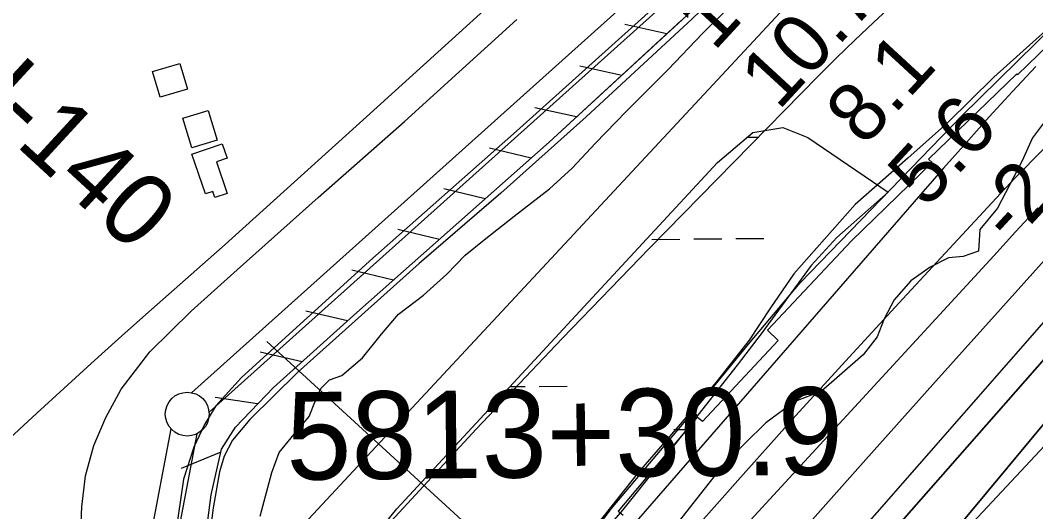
# Model space of a CAD drawing. Extents: x 3598634 to 3636690, y 517270 to 542944.
# Drawn here: x 3606399 to 3607559, y 531870 to 532431 of the extents above; entities that cross this region are included whole.
import ezdxf

# ---------------------------------------------------------------- set-up
doc = ezdxf.new("R2010")
doc.units = 0
for name, color, linetype in [('V-BLDG-OTLN', 7, 'Continuous'), ('V-FLOD-BASE', 7, 'Continuous'), ('V-LEVE-TOET', 7, 'Continuous'), ('V-RIVR-EDGE', 7, 'Continuous'), ('V-RIVR-RANG', 7, 'Continuous'), ('V-RIVR-RANG-IDEN', 7, 'Continuous'), ('V-ROAD-CNTR', 7, 'Continuous'), ('V-RRAP-FSHR', 7, 'Continuous'), ('V-RRAP-RVMT', 7, 'Continuous'), ('V-SITE-VEGE', 7, 'Continuous'), ('V-SURV-IDEN', 7, 'Continuous'), ('V-SURV-LINE', 7, 'Continuous'), ('V-TOPO-DPTH', 7, 'Continuous'), ('V-TOPO-MINR', 7, 'Continuous'), ('V-TOPO-WATR', 7, 'Continuous'), ('V-WETL-SWMP', 7, 'Continuous')]:
    doc.layers.add(name, color=color, linetype=linetype)

msp = doc.modelspace()

# ---------------------------------------------------------------- linework, layer by layer
at = {"layer": 'V-BLDG-OTLN'}
for points in [[(3606558.9, 532342.9), (3606550.2, 532372.2), (3606581.3, 532381.5), (3606590.1, 532352.2)], [(3606614, 532327.8), (3606624.1, 532293.7), (3606595, 532285), (3606584.9, 532319.1)], [(3606623.4, 532269.2), (3606635.5, 532233.1), (3606621.5, 532228.3), (3606619.1, 532235.3), (3606610.6, 532232.5), (3606595.3, 532277.8), (3606630, 532289.5), (3606635.4, 532273.2)]]:
    msp.add_lwpolyline(points, close=True, dxfattribs=at)
at = {"layer": 'V-FLOD-BASE'}
msp.add_lwpolyline([(3607131.3, 532452.3), (3606965.8, 532304), (3606801.7, 532159.1), (3606651.9, 532023), (3606622.6, 531990.5), (3606609.6, 531969.5), (3606597.3, 531943.7), (3606585.6, 531907.1), (3606579.4, 531865), (3606569.7, 531795.7), (3606561.5, 531769.2), (3606546.5, 531738.7), (3606517.8, 531695.3), (3606461.2, 531631), (3606393.8, 531563.9)], dxfattribs=at)
at = {"layer": 'V-LEVE-TOET'}
for points in [[(3607580.8, 532806.7), (3607479.3, 532720), (3607360.9, 532617.8), (3607272.3, 532533.8), (3607166.7, 532432.2), (3607045.5, 532320.5), (3606948.1, 532233.2), (3606854.9, 532153.3), (3606715.9, 532028.7), (3606661.5, 531975.2), (3606641.7, 531951.5), (3606632.1, 531933.2), (3606626.6, 531915.5), (3606619.7, 531874.1)], [(3606347.9, 531665.3), (3606407.9, 531731.6), (3606434.4, 531762.1), (3606446, 531777), (3606457.7, 531803.5), (3606463.8, 531824.5), (3606468.6, 531848.3), (3606469.4, 531875.5), (3606473.6, 531910.8), (3606483.2, 531945.4), (3606496.9, 531977.3), (3606514.6, 532009.8), (3606547.3, 532052.5), (3606594.3, 532098.6), (3606646.8, 532146), (3606739.4, 532228.6), (3606838.1, 532315.2), (3606966.2, 532431.7)], [(3606619.7, 531874.1), (3606606.5, 531772.9), (3606598.3, 531747.8), (3606579.2, 531711.9), (3606555.3, 531673.9), (3606532.1, 531646.1), (3606494.7, 531605.5), (3606428.6, 531534.3), (3606332.5, 531435.4), (3606250.1, 531349.4), (3606213.3, 531314.2), (3606139.1, 531242.4), (3606000.1, 531109.7), (3605968.1, 531071.7), (3605947.6, 531042.6), (3605936, 531022.9), (3605928.5, 531002.6), (3605923.7, 530974), (3605909.9, 530921.8), (3605898.3, 530885.8), (3605874.4, 530845.1), (3605845.1, 530801.7), (3605764.7, 530709.6)]]:
    msp.add_lwpolyline(points, dxfattribs=at)
at = {"layer": 'V-RIVR-EDGE'}
msp.add_lwpolyline([(3607568.7, 532314.8), (3607555.2, 532296.4), (3607542.9, 532269.5), (3607515.2, 532216.3), (3607494.9, 532191.8), (3607493.6, 532167.3), (3607475.8, 532161.2), (3607459.3, 532159.4), (3607438.4, 532149.1), (3607416.3, 532133.2), (3607397.3, 532111.8), (3607385.6, 532089.8), (3607377.6, 532069.6), (3607361.6, 532048.8), (3607313.7, 532007.2), (3607283.6, 531995.7), (3607250.5, 531971.2), (3607202.6, 531924.2), (3607175.5, 531889.9), (3607152.2, 531860)], dxfattribs=at)
at = {"layer": 'V-RIVR-RANG'}
msp.add_line((3606681, 532064.1), (3607374.3, 531429.2), dxfattribs=at)
at = {"layer": 'V-ROAD-CNTR'}
msp.add_lwpolyline([(3606387.4, 531953.7), (3606418.2, 531982.2), (3606449.1, 532010.6), (3606480.2, 532038.9), (3606511.3, 532067), (3606542.6, 532095), (3606633.2, 532174.9), (3606794.6, 532320.4), (3606941, 532453.2)], dxfattribs=at)
at = {"layer": 'V-RRAP-FSHR'}
for p, q in [((3607137.5, 532415.2), (3607089.8, 532425.7)), ((3607086.1, 532367.8), (3607038.4, 532378.3)), ((3607034.6, 532320.4), (3606986.9, 532330.8)), ((3606982.7, 532273.4), (3606935.2, 532284.8)), ((3606930.3, 532227), (3606882.8, 532238.4)), ((3606877.9, 532180.6), (3606830.4, 532192)), ((3606825.4, 532134.2), (3606777.9, 532145.6)), ((3606773.1, 532087.8), (3606725.5, 532098.8)), ((3606721, 532041), (3606673.4, 532052)), ((3606670.3, 531992.8), (3606622, 532000.3)), ((3606628.2, 531937.8), (3606582.9, 531919.3))]:
    msp.add_line(p, q, dxfattribs=at)
for points in [[(3605820.9, 530227.4), (3606036.1, 530488.4), (3606189.3, 530713.3), (3606419.6, 531040.7), (3606531.1, 531185.8), (3606653.3, 531360.7), (3606830.6, 531572), (3606913.7, 531664.9), (3606995.7, 531768), (3607074.2, 531873.3), (3607165.6, 531981.6), (3607231, 532060.9), (3607289.9, 532131), (3607473.9, 532321.1), (3607836.1, 532677), (3607900.4, 532747.2), (3608145, 532976.3), (3608226.2, 533101.7), (3608431.6, 533291.6), (3608655.7, 533489.7), (3608731.3, 533575.9), (3608845.3, 533667.2), (3608960.4, 533749.3)], [(3604875.1, 529685.7), (3605090, 529929.6), (3605236.8, 530108), (3605464.9, 530364.9), (3605751.9, 530707.6), (3605853.7, 530832.3), (3605888.7, 530881.3), (3605915.9, 530970.2), (3605940.9, 531032.9), (3605978.4, 531089.9), (3606027.7, 531141.9), (3606259.9, 531369.8), (3606464.4, 531577.9), (3606550.8, 531679.8), (3606587.9, 531739.7), (3606600.6, 531772.1), (3606609.7, 531830.4), (3606617.1, 531889.3), (3606629, 531941.4), (3606644.9, 531966.5), (3606688.5, 532011.7), (3606783.7, 532097.3), (3607003.1, 532291.4), (3607274.6, 532541.5)], [(3606562, 531697.8), (3606587.9, 531739.7), (3606600.6, 531772.1), (3606609.7, 531830.4), (3606617.1, 531889.3), (3606629, 531941.4), (3606644.9, 531966.5), (3606688.5, 532011.7), (3606783.7, 532097.3), (3607003.1, 532291.4), (3607153.9, 532430.3)]]:
    msp.add_lwpolyline(points, dxfattribs=at)
at = {"layer": 'V-RRAP-RVMT'}
for p, q in [((3607721.9, 532546.8), (3607538.2, 532368.5)), ((3607537.1, 532369.4), (3607436.5, 532272.2)), ((3607538.2, 532368.5), (3607537.1, 532369.4)), ((3607440.5, 532268.2), (3607348.3, 532179.1)), ((3607436.5, 532272.2), (3607440.5, 532268.2)), ((3607348.3, 532179.1), (3607252.7, 532077)), ((3607252.7, 532077), (3607264.7, 532065.4)), ((3607264.7, 532065.4), (3607178.3, 531972.8)), ((3607172.2, 531977.8), (3607082.1, 531870.6)), ((3607178.3, 531972.8), (3607172.2, 531977.8)), ((3607487.4, 531858), (3607568.7, 531945)), ((3607082.1, 531870.6), (3607087.7, 531865.8))]:
    msp.add_line(p, q, dxfattribs=at)
at = {"layer": 'V-SITE-VEGE'}
for p, q in [((3607178.3, 532415.4), (3607209, 532446)), ((3607606, 532451.1), (3607511.1, 532365.7)), ((3607139.2, 532374.4), (3607178.3, 532415.4)), ((3607091, 532326.5), (3607139.2, 532374.4)), ((3607511.1, 532365.7), (3607458, 532313.6)), ((3607056.1, 532290.4), (3607091, 532326.5)), ((3607458, 532313.6), (3607412.6, 532273.4)), ((3607029.5, 532261.9), (3607056.1, 532290.4)), ((3607412.6, 532273.4), (3607352.6, 532220.6)), ((3607003.7, 532238.3), (3607029.5, 532261.9)), ((3606963.2, 532207.1), (3607003.7, 532238.3)), ((3607352.6, 532220.6), (3607282.7, 532141.4)), ((3606929, 532180), (3606963.2, 532207.1)), ((3606907.4, 532162.7), (3606929, 532180)), ((3606886.4, 532141.1), (3606907.4, 532162.7)), ((3606859.9, 532116.8), (3606886.4, 532141.1)), ((3607282.7, 532141.4), (3607256.1, 532102.5)), ((3606831.3, 532095.3), (3606859.9, 532116.8)), ((3606811.7, 532072.4), (3606831.3, 532095.3)), ((3607256.1, 532102.5), (3607231.6, 532065.6)), ((3606790, 532045.3), (3606811.7, 532072.4)), ((3607231.6, 532065.6), (3607193.9, 532017.7)), ((3606766.3, 532025.2), (3606790, 532045.3)), ((3606752.3, 532020.3), (3606766.3, 532025.2)), ((3606742.6, 532010.6), (3606752.3, 532020.3)), ((3607193.9, 532017.7), (3607150.6, 531967)), ((3606736.3, 531996.7), (3606742.6, 532010.6)), ((3606729.2, 531978.6), (3606736.3, 531996.7)), ((3606715.3, 531962.6), (3606729.2, 531978.6)), ((3607150.6, 531967), (3607105.1, 531914.9)), ((3606695, 531937.6), (3606715.3, 531962.6)), ((3606686.6, 531914.7), (3606695, 531937.6)), ((3606673.2, 531864.6), (3606686.6, 531914.7)), ((3607105.1, 531914.9), (3607044.3, 531838.4))]:
    msp.add_line(p, q, dxfattribs=at)
at = {"layer": 'V-SURV-LINE'}
for points in [[(3606594.7, 532005.7), (3607952.8, 533222.8)], [(3607972.9, 533200.5), (3606614.8, 531983.4)], [(3606541.2, 531804.1), (3606571.4, 531964.4)], [(3606600.9, 531958.8), (3606570.6, 531798.5)]]:
    msp.add_lwpolyline(points, dxfattribs=at)
msp.add_circle((3606589.9, 531981.2), 25, dxfattribs=at)
at = {"layer": 'V-TOPO-DPTH'}
for points in [[(3607983.4, 532707.3), (3607541.5, 532257), (3607535.7, 532251.1), (3607529.9, 532245.1), (3607524.2, 532239.1), (3607518.5, 532233), (3607407, 532112.8), (3607345.8, 532046.4), (3607285, 531979.6), (3607224.8, 531912.4), (3607164.8, 531844.8), (3606773.7, 531400.4), (3606760.3, 531385), (3606747.1, 531369.4), (3606734.1, 531353.7), (3606064.8, 530299.3)], [(3606064.8, 530299.3), (3606734.1, 531353.7), (3606747.1, 531369.4), (3606760.3, 531385), (3606773.7, 531400.4), (3607164.8, 531844.8), (3607224.8, 531912.4), (3607285, 531979.6), (3607345.8, 532046.4), (3607407, 532112.8), (3607518.5, 532233), (3607524.2, 532239.1), (3607529.9, 532245.1), (3607535.7, 532251.1), (3607541.5, 532257), (3607983.4, 532707.3)], [(3607395, 532447.9), (3607373.4, 532428.1), (3607352.1, 532408), (3607331.1, 532387.5), (3607310.4, 532366.8), (3607117.7, 532170.5), (3607018.2, 532067.7), (3606919.8, 531964), (3606822.7, 531858.9), (3606726.7, 531752.9), (3606543.7, 531548.1), (3606539.9, 531543.8), (3606536.2, 531539.5), (3606532.5, 531535.2), (3606528.8, 531530.8), (3606474, 531465.6), (3606443.1, 531428.5), (3606412.5, 531391.1), (3606382.4, 531353.3), (3606352.5, 531315.4), (3605991.8, 530851.1), (3605962, 530812.4)], [(3607575.6, 532164.4), (3607441.4, 532015.1), (3607364.9, 531929.5), (3607288.8, 531843.7), (3607213.3, 531757.4), (3607138.1, 531670.7), (3606851.2, 531338.4), (3606838, 531322.6), (3606825.1, 531306.5), (3606812.7, 531290.1), (3606800.6, 531273.4), (3606710.9, 531145), (3606687.7, 531111.2), (3606665, 531077.1), (3606642.9, 531042.5), (3606621.2, 531007.7), (3606599.5, 530972.8), (3606577.5, 530938.2), (3606555, 530903.9), (3606532.1, 530869.9), (3606459.8, 530764.4)], [(3606459.8, 530764.4), (3606532.1, 530869.9), (3606555, 530903.9), (3606577.5, 530938.2), (3606599.5, 530972.8), (3606621.2, 531007.7), (3606642.9, 531042.5), (3606665, 531077.1), (3606687.7, 531111.2), (3606710.9, 531145), (3606800.6, 531273.4), (3606812.7, 531290.1), (3606825.1, 531306.5), (3606838, 531322.6), (3606851.2, 531338.4), (3607138.1, 531670.7), (3607213.3, 531757.4), (3607288.8, 531843.7), (3607364.9, 531929.5), (3607441.4, 532015.1), (3607575.6, 532164.4)], [(3606570.4, 530814.7), (3606635, 530902), (3606699.7, 530989.3), (3606764.3, 531076.6), (3606862.8, 531209.4), (3606878.4, 531230.2), (3606894.2, 531250.8), (3606910.2, 531271.2), (3606926.4, 531291.5), (3607025.4, 531413.8), (3607091.8, 531494.7), (3607158.8, 531575.1), (3607226.8, 531654.6), (3607295.4, 531733.7), (3607612.9, 532094.7)], [(3607612.9, 532094.7), (3607295.4, 531733.7), (3607226.8, 531654.6), (3607158.8, 531575.1), (3607091.8, 531494.7), (3607025.4, 531413.8), (3606926.4, 531291.5), (3606910.2, 531271.2), (3606894.2, 531250.8), (3606878.4, 531230.2), (3606862.8, 531209.4), (3606764.3, 531076.6), (3606699.7, 530989.3), (3606635, 530902), (3606570.4, 530814.7)], [(3606603.6, 530726), (3606689.7, 530846.3), (3606775.3, 530967), (3606917.5, 531169), (3606931.6, 531188.8), (3606945.8, 531208.6), (3606960.2, 531228.3), (3606974.8, 531247.9), (3606989.5, 531267.3), (3607004.4, 531286.6), (3607019.5, 531305.7), (3607034.8, 531324.7), (3607113.6, 531421.1), (3607168.4, 531488.1), (3607223.5, 531555.1), (3607278.6, 531621.8), (3607333.9, 531688.5), (3607575.6, 531979.3)], [(3607575.6, 531979.3), (3607333.9, 531688.5), (3607278.6, 531621.8), (3607223.5, 531555.1), (3607168.4, 531488.1), (3607113.6, 531421.1), (3607034.8, 531324.7), (3607019.5, 531305.7), (3607004.4, 531286.6), (3606989.5, 531267.3), (3606974.8, 531247.9), (3606960.2, 531228.3), (3606945.8, 531208.6), (3606931.6, 531188.8), (3606917.5, 531169), (3606775.3, 530967), (3606689.7, 530846.3), (3606603.6, 530726)]]:
    msp.add_lwpolyline(points, dxfattribs=at)
at = {"layer": 'V-TOPO-MINR'}
for points in [[(3607781.2, 532936.8), (3607320.2, 532493.6), (3607305.4, 532479), (3607290.7, 532464.3), (3607276.2, 532449.4), (3607261.9, 532434.3), (3606702.8, 531834.1), (3606665.1, 531793.2), (3606627.6, 531751.9), (3606590.6, 531710.2), (3606554, 531668.3), (3606534.8, 531646.1), (3606508, 531615), (3606481.3, 531583.8), (3606454.7, 531552.5), (3606428.2, 531521.1), (3605876.9, 530865)], [(3607395, 532447.9), (3607373.4, 532428.1), (3607352.1, 532408), (3607331.1, 532387.5), (3607310.4, 532366.8), (3607117.7, 532170.5), (3607018.2, 532067.7), (3606919.8, 531964), (3606822.7, 531858.9), (3606726.7, 531752.9), (3606543.7, 531548.1), (3606539.9, 531543.8), (3606536.2, 531539.5), (3606532.5, 531535.2), (3606528.8, 531530.8), (3606474, 531465.6), (3606443.1, 531428.5), (3606412.5, 531391.1), (3606382.4, 531353.3), (3606352.5, 531315.4), (3605991.8, 530851.1), (3605962, 530812.4)], [(3607558.8, 532378.1), (3607532.2, 532349.4), (3607505.8, 532320.3), (3607479.6, 532291.2), (3607453.6, 532261.9), (3607427.8, 532232.4), (3606790.6, 531500), (3606776.6, 531483.7), (3606762.7, 531467.3), (3606748.9, 531450.8), (3606735.2, 531434.2), (3606721.7, 531417.5), (3606708.3, 531400.7), (3606695, 531383.8), (3606681.9, 531366.8), (3606306.8, 530876.9), (3606243.5, 530794)], [(3607561.2, 532216.5), (3607535.9, 532189.2), (3607510.8, 532161.9), (3607206.4, 531831.2), (3607133.3, 531751.5), (3607060.3, 531671.7), (3606987.6, 531591.6), (3606915, 531511.4), (3606777.3, 531358.8), (3606773.8, 531354.8), (3606770.3, 531350.7), (3606174.6, 530407.7), (3606146.8, 530369.8), (3606083.9, 530285.2), (3606075.9, 530274.6), (3606067.9, 530264), (3606059.9, 530253.4), (3606051.8, 530242.9), (3605366.7, 529350.5)], [(3607575.6, 532164.4), (3607441.4, 532015.1), (3607364.9, 531929.5), (3607288.8, 531843.7), (3607213.3, 531757.4), (3607138.1, 531670.7), (3606851.2, 531338.4), (3606838, 531322.6), (3606825.1, 531306.5), (3606812.7, 531290.1), (3606800.6, 531273.4), (3606710.9, 531145), (3606687.7, 531111.2), (3606665, 531077.1), (3606642.9, 531042.5), (3606621.2, 531007.7), (3606599.5, 530972.8), (3606577.5, 530938.2), (3606555, 530903.9), (3606532.1, 530869.9), (3606459.8, 530764.4)], [(3607578.7, 532098.9), (3606921.1, 531348.1), (3606911, 531336.4), (3606901.1, 531324.6), (3606891.3, 531312.7), (3606881.6, 531300.7), (3606872.1, 531288.5), (3606862.7, 531276.2), (3606853.5, 531263.7), (3606844.5, 531251.2), (3606663.3, 530996), (3606571.7, 530867.8), (3606479.6, 530740)], [(3607612.9, 532094.7), (3607295.4, 531733.7), (3607226.8, 531654.6), (3607158.8, 531575.1), (3607091.8, 531494.7), (3607025.4, 531413.8), (3606926.4, 531291.5), (3606910.2, 531271.2), (3606894.2, 531250.8), (3606878.4, 531230.2), (3606862.8, 531209.4), (3606764.3, 531076.6), (3606699.7, 530989.3), (3606635, 530902), (3606570.4, 530814.7)], [(3607575.6, 531979.3), (3607333.9, 531688.5), (3607278.6, 531621.8), (3607223.5, 531555.1), (3607168.4, 531488.1), (3607113.6, 531421.1), (3607034.8, 531324.7), (3607019.5, 531305.7), (3607004.4, 531286.6), (3606989.5, 531267.3), (3606974.8, 531247.9), (3606960.2, 531228.3), (3606945.8, 531208.6), (3606931.6, 531188.8), (3606917.5, 531169), (3606775.3, 530967), (3606689.7, 530846.3), (3606603.6, 530726)]]:
    msp.add_lwpolyline(points, dxfattribs=at)
at = {"layer": 'V-TOPO-WATR'}
msp.add_lwpolyline([(3607983.4, 532707.3), (3607541.5, 532257), (3607535.7, 532251.1), (3607529.9, 532245.1), (3607524.2, 532239.1), (3607518.5, 532233), (3607407, 532112.8), (3607345.8, 532046.4), (3607285, 531979.6), (3607224.8, 531912.4), (3607164.8, 531844.8), (3606773.7, 531400.4), (3606760.3, 531385), (3606747.1, 531369.4), (3606734.1, 531353.7), (3606064.8, 530299.3)], dxfattribs=at)
at = {"layer": 'V-WETL-SWMP'}
for p, q in [((3607229.1, 532297.1), (3607242.6, 532297.2)), ((3607120.3, 532180.6), (3607152.3, 532180.9)), ((3607168.3, 532181.1), (3607200.3, 532181.4)), ((3607216.3, 532181.5), (3607248.3, 532181.8)), ((3606958.4, 532012.6), (3606975.9, 532012.8)), ((3606991.9, 532012.9), (3607023.9, 532013.2)), ((3607145.7, 531963.6), (3607160.2, 531963.8))]:
    msp.add_line(p, q, dxfattribs=at)
for points in [[(3604750.8, 529468.5), (3605243.2, 530023.9), (3606142.1, 531025.9), (3606829.2, 531873.3), (3607195.6, 532268.4), (3607235.7, 532302.8), (3607270.1, 532308.5), (3607298.7, 532297), (3607390.2, 532234.7)], [(3607390.2, 532234.7), (3607331.7, 532182.9), (3607302.4, 532151), (3607246.4, 532074.5), (3607217.8, 532037), (3607160.4, 531964), (3607124.8, 531918.9), (3607087, 531871.6), (3607047.2, 531825.8)]]:
    msp.add_lwpolyline(points, dxfattribs=at)
msp.add_arc((3607140.5, 531964.1), 35.2, 25.3652, 41.3052, dxfattribs=at)

# ---------------------------------------------------------------- texts
at = {"layer": 'V-RIVR-RANG'}
for s, p in [('17.2', (3607191.4, 532394.2)), ('10.7', (3607265.1, 532326.6)), ('8.1', (3607363, 532285.3)), ('5.6', (3607433.9, 532214.6)), ('-2', (3607531.5, 532173))]:
    msp.add_text(s, height=67, rotation=47.3583, dxfattribs=at).set_placement(p)
at = {"layer": 'V-RIVR-RANG-IDEN'}
msp.add_text('U-140', height=83, rotation=317.3753, dxfattribs=at).set_placement((3606306.4, 532368.2))
at = {"layer": 'V-SURV-IDEN'}
msp.add_text('5813+30.9', height=100, rotation=0.554, dxfattribs=at).set_placement((3606703.4, 531906.2))

doc.saveas('drawing.dxf')
